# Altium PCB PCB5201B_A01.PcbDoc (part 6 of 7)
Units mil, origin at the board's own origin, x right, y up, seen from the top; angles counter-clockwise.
Board outline 4527.56 x 2362.2 mil, 6 copper layers (Top Layer, GND Layer 2, Signal Layer 3, Signal Layer 4, VCC Layer 5, Bottom Layer), stack 61.221 mil thick; 361 components, 250 nets, 1223 pads, 1068 vias.
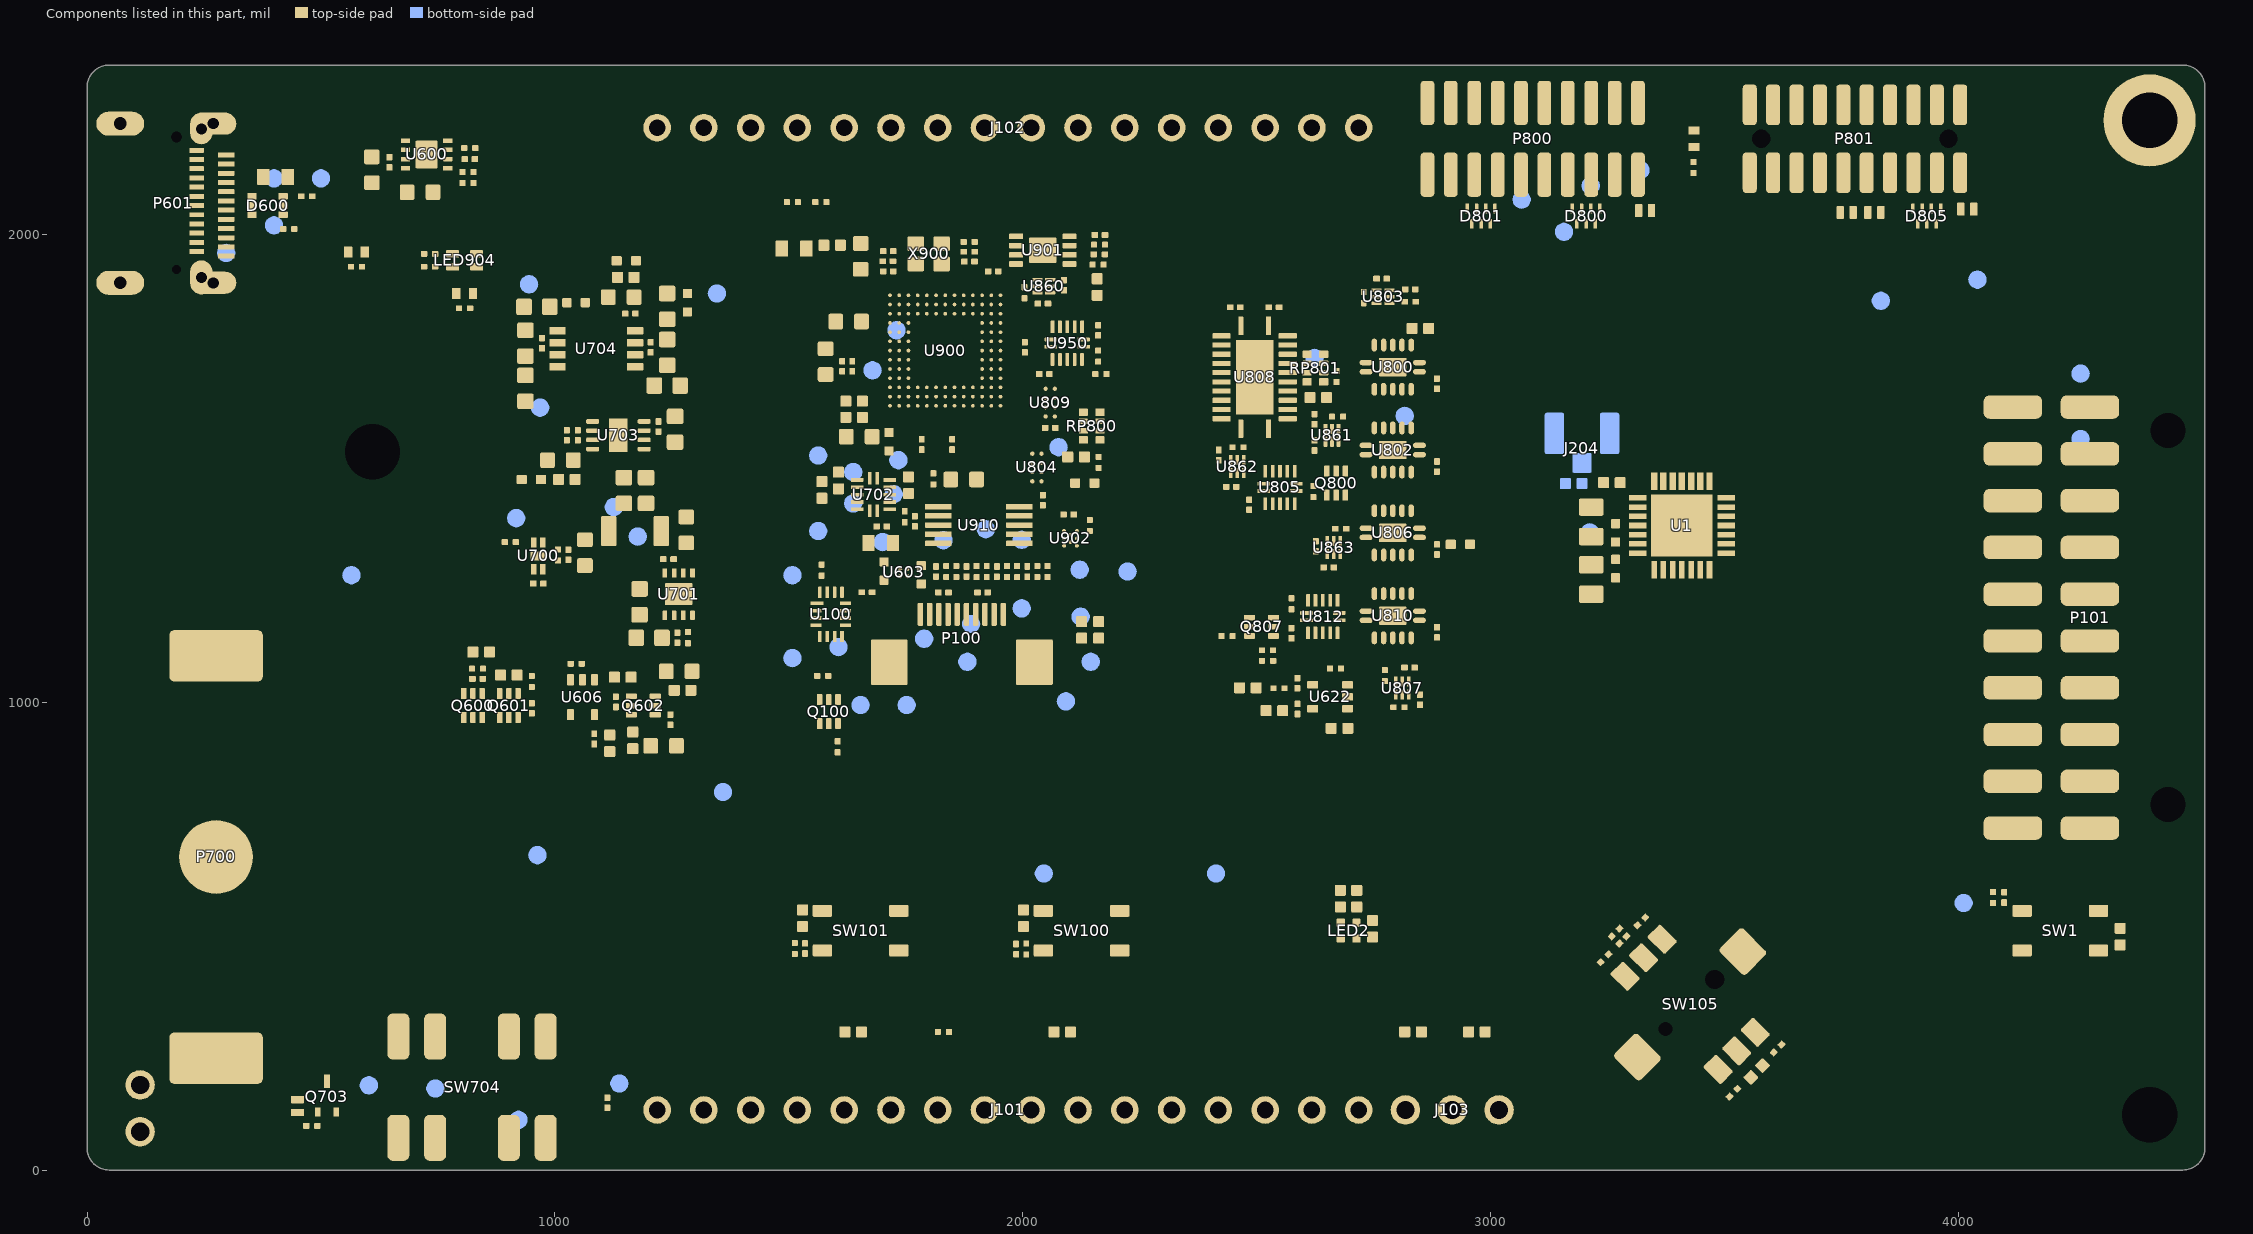
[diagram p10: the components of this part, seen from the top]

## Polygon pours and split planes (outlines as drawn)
VMCU on VCC Layer 5 "VMCU_L05_P027" (solid, remove dead copper, pour order 27): 3067.91,1562.99 3084.65,1579.72 4004.92,1579.72 4033.46,1608.27 4033.46,2333.66 4062.01,2362.2 4527.56,2362.2 4527.56,0 828.74,0 826.77,0 798.23,28.54 798.23,248.03 808.07,257.87 1142.72,257.87 1163.39,278.54 1163.39,914.37 1183.07,934.06 3031.5,934.06 3067.91,970.47
3V3 on VCC Layer 5 "3V3_L05_P024" (solid, remove dead copper, pour order 24): 337.6,1413.18 340.76,1416.34 706.69,1416.34 1187.01,1416.34 1322.83,1280.51 1633.86,1280.51 1752.41,1399.06 1752.41,1657.64 1680.76,1730.32 1482.28,1730.32 1422.93,1789.67 714.11,1789.67 612.2,1892.92 612.2,2059.05 628.54,2075.39 2514.37,2075.39 2694.94,2255.96 2781.74,2255.85 3058.36,1983.27 3765.75,1983.27 3913.39,2130.91 3913.39,2324.8 3930.12,2341.54 4013.78,2341.54 4024.61,2330.71 4024.61,1617.13 3997.05,1589.57 3074.8,1589.57 3056.1,1570.87 3057.09,1567.91 3057.09,975.39 3026.57,944.88 1175.2,944.88 1153.54,923.23 1153.54,914.37 1153.54,286.42 1153.54,284.45 1136.81,266.73 768.7,266.73 703.74,331.69 703.74,1040.35 337.6,1406.5
5V on VCC Layer 5 "5V_L05_P005" (solid, remove dead copper, pour order 5): 1676.18,1720.47 1475.88,1720.47 1416.86,1780.51 710.63,1780.51 604.33,1886.81 604.33,2062.99 625,2083.66 2508.86,2083.66 2690.94,2265.75 2786.42,2265.75 3061.02,1991.14 3763.78,1991.14 3907.48,2134.84 3907.48,2326.77 3893.7,2340.55 308.07,2340.55 301.18,2333.66 301.18,1440.94 316.93,1425.2 1191.93,1425.2 1326.77,1290.35 1629.92,1290.35 1743.11,1403.54 1743.11,1653.54
GND on VCC Layer 5 "VCC Layer 5-GND" (solid, remove dead copper, pour order 28): 19.68,19.68 757.87,19.68 767.72,29.53 767.72,227.36 673.23,321.85 673.23,1030.51 279.53,1424.21 279.53,2342.52 37.4,2342.52 19.68,2324.8 19.68,1393.7
GND on Top Layer "GND_L01_P021" (solid, remove dead copper, pour order 21): 0,0 0,2362.2 4921.26,2362.2 4921.26,0
USBC_VBUS on Top Layer "USBC_VBUS_L01_P020" (solid, remove dead copper, pour order 20): 387.8,2170.28 387.8,2109.25 347.44,2109.25 330.71,2125.98 330.71,2154.53 354.33,2178.15 382.55,2178.15
5V on Top Layer "5V_L01_P019" (solid, remove dead copper, pour order 19): 417.32,2107.28 417.32,2168.31 436.02,2187.01 469.49,2187.01 483.27,2173.23 483.27,2112.2 482.28,2112.2 477.36,2107.28 420.28,2107.28
5V on Top Layer "5V_L01_P018" (solid, remove dead copper, pour order 18): 565.94,2150.59 550.2,2166.34 550.2,2211.61 563.98,2225.39 644.68,2225.39 661.42,2208.66 661.42,2174.21 647.64,2160.43 619.09,2160.43 619.09,2153.54 616.14,2150.59
3V3 on Top Layer "3V3_L01_P017" (solid, remove dead copper, pour order 17): 670.28,2145.67 662.4,2137.8 662.4,2120.08 638.78,2096.46 638.78,2042.32 651.57,2029.53 706.69,2029.53 718.5,2041.34 718.5,2068.9 699.8,2087.6 699.8,2133.86 687.99,2145.67
VMCU_R on Top Layer "VMCU_R_L01_P016" (solid, remove dead copper, pour order 16): 1240.16,1267.72 1239.17,1268.7 1239.17,1291.34 1235.24,1295.28 1222.44,1295.28 1190.94,1326.77 1153.54,1326.77 1139.76,1312.99 1139.76,1282.48 1155.51,1266.73 1239.17,1266.73 1240.16,1267.72 1240.16,1268.7
VMCU_R on Top Layer "VMCU_R_L01_P015" (solid, remove dead copper, pour order 15): 1201.77,1396.65 1195.87,1390.75 1195.87,1348.43 1176.18,1328.74 1154.53,1328.74 1139.76,1313.98 1139.76,1307.09 1148.62,1298.23 1186.02,1298.23 1222.44,1334.65 1239.17,1334.65 1243.11,1338.58 1243.11,1396.65
VMCU_S on Top Layer "VMCU_S_L01_P014" (solid, remove dead copper, pour order 14): 1130.91,1397.64 1128.94,1395.67 1128.94,1335.63 1072.83,1335.63 1068.9,1331.69 1053.15,1331.69 1042.32,1320.87 1041.34,1321.85 995.08,1321.85 987.2,1329.72 987.2,1375.98 1007.87,1396.65 1125,1396.65 1125.98,1397.64
5V on Top Layer "5V_L01_P013" (solid, remove dead copper, pour order 13): 1248.03,1302.17 1248.03,1323.82 1265.75,1341.54 1265.75,1352.36 1269.68,1356.3 1309.06,1356.3 1327.76,1375 1340.55,1375 1351.38,1364.17 1351.38,1314.96 1331.69,1295.28 1269.69,1295.28 1262.8,1302.17
AEM_VMCU on Top Layer "AEM_VMCU_L01_P002" (solid, remove dead copper, pour order 2): 959.65,1294.29 958.66,1295.28 931.1,1295.28 917.32,1281.5 917.32,1245.08 909.45,1237.2 909.45,1220.47 918.31,1211.61 956.69,1211.61 966.54,1221.46 966.54,1240.16 959.65,1247.05
GND on Signal Layer 3 "GND_L03_P025" (solid, remove dead copper, pour order 25): 0,0 0,2362.2 4921.26,2362.2 4921.26,0
3V3 on Signal Layer 3 "3V3_L03_P022" (solid, remove dead copper, pour order 22): 714.57,2034.45 729.33,2049.21 729.33,2132.87 696.85,2165.35 696.85,2238.19 678.15,2256.89 641.73,2256.89 626.97,2242.13 626.97,2170.28 650.59,2146.65 650.59,2038.39 654.53,2034.45
GND on GND Layer 2 "GND_L02_P009" (solid, remove dead copper, pour order 9): 0,0 0,2362.2 4921.26,2362.2 4921.26,0
GND on Bottom Layer "GND_L06_P008" (solid, remove dead copper, pour order 8): 0,0 0,2362.2 4921.26,2362.2 4921.26,0
GND on Signal Layer 4 "GND_L04_P012" (solid, remove dead copper, pour order 12): 0,0 0,2362.2 4921.26,2362.2 4921.26,0

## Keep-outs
Bottom Layer:
  region: 500.01,2139.76 cw(c500.01,2120.07) 519.7,2120.08 cw(c500.01,2120.08) 500.01,2100.39 cw(c500.01,2120.07) 480.33,2120.07 cw(c500.02,2120.07)
  region: 1287.04,228.43 ccw(c1318.54,228.43) 1318.54,196.94 ccw(c1318.54,228.43) 1350.03,228.43 ccw(c1318.54,228.43) 1318.54,259.93 ccw(c1318.54,228.43)
  region: 1387.04,228.43 ccw(c1418.54,228.43) 1418.54,196.94 ccw(c1418.54,228.43) 1450.03,228.43 ccw(c1418.54,228.43) 1418.54,259.93 ccw(c1418.54,228.43)
  region: 1487.04,228.43 ccw(c1518.54,228.43) 1518.54,196.94 ccw(c1518.54,228.43) 1550.03,228.43 ccw(c1518.54,228.43) 1518.54,259.93 ccw(c1518.54,228.43)
  region: 1587.04,228.43 ccw(c1618.54,228.43) 1618.54,196.94 ccw(c1618.54,228.43) 1650.03,228.43 ccw(c1618.54,228.43) 1618.54,259.93 ccw(c1618.54,228.43)
  region: 1687.04,228.43 ccw(c1718.54,228.43) 1718.54,196.94 ccw(c1718.54,228.43) 1750.03,228.43 ccw(c1718.54,228.43) 1718.54,259.93 ccw(c1718.54,228.43)
  region: 1787.04,228.43 ccw(c1818.54,228.43) 1818.54,196.94 ccw(c1818.54,228.43) 1850.03,228.43 ccw(c1818.54,228.43) 1818.54,259.93 ccw(c1818.54,228.43)
  region: 1887.04,228.43 ccw(c1918.54,228.43) 1918.54,196.94 ccw(c1918.54,228.43) 1950.03,228.43 ccw(c1918.54,228.43) 1918.54,259.93 ccw(c1918.54,228.43)
  region: 1987.04,228.43 ccw(c2018.54,228.43) 2018.54,196.94 ccw(c2018.54,228.43) 2050.03,228.43 ccw(c2018.54,228.43) 2018.54,259.93 ccw(c2018.54,228.43)
  region: 2087.04,228.43 ccw(c2118.54,228.43) 2118.54,196.94 ccw(c2118.54,228.43) 2150.03,228.43 ccw(c2118.54,228.43) 2118.54,259.93 ccw(c2118.54,228.43)
  region: 2187.04,228.43 ccw(c2218.54,228.43) 2218.54,196.94 ccw(c2218.54,228.43) 2250.03,228.43 ccw(c2218.54,228.43) 2218.54,259.93 ccw(c2218.54,228.43)
  region: 2287.04,228.43 ccw(c2318.54,228.43) 2318.54,196.94 ccw(c2318.54,228.43) 2350.03,228.43 ccw(c2318.54,228.43) 2318.54,259.93 ccw(c2318.54,228.43)
  region: 2387.04,228.43 ccw(c2418.54,228.43) 2418.54,196.94 ccw(c2418.54,228.43) 2450.03,228.43 ccw(c2418.54,228.43) 2418.54,259.93 ccw(c2418.54,228.43)
  region: 2487.04,228.43 ccw(c2518.54,228.43) 2518.54,196.94 ccw(c2518.54,228.43) 2550.03,228.43 ccw(c2518.54,228.43) 2518.54,259.93 ccw(c2518.54,228.43)
  region: 2587.04,228.43 ccw(c2618.54,228.43) 2618.54,196.94 ccw(c2618.54,228.43) 2650.03,228.43 ccw(c2618.54,228.43) 2618.54,259.93 ccw(c2618.54,228.43)
  region: 2687.04,228.43 ccw(c2718.54,228.43) 2718.54,196.94 ccw(c2718.54,228.43) 2750.03,228.43 ccw(c2718.54,228.43) 2718.54,259.93 ccw(c2718.54,228.43)
  region: 1187.04,228.43 ccw(c1218.54,228.43) 1218.54,196.94 ccw(c1218.54,228.43) 1250.03,228.43 ccw(c1218.54,228.43) 1218.54,259.93 ccw(c1218.54,228.43)
  region: 1187.04,128.43 ccw(c1218.54,128.43) 1218.54,96.94 ccw(c1218.54,128.43) 1250.03,128.43 ccw(c1218.54,128.43) 1218.54,159.93 ccw(c1218.54,128.43)
  region: 1187.04,128.43 ccw(c1218.54,128.43) 1218.54,96.94 ccw(c1218.54,128.43) 1250.03,128.43 ccw(c1218.54,128.43) 1218.54,159.93 ccw(c1218.54,128.43)
  region: 1287.04,128.43 ccw(c1318.54,128.43) 1318.54,96.94 ccw(c1318.54,128.43) 1350.03,128.43 ccw(c1318.54,128.43) 1318.54,159.93 ccw(c1318.54,128.43)
  region: 1387.04,128.43 ccw(c1418.54,128.43) 1418.54,96.94 ccw(c1418.54,128.43) 1450.03,128.43 ccw(c1418.54,128.43) 1418.54,159.93 ccw(c1418.54,128.43)
  region: 1487.04,128.43 ccw(c1518.54,128.43) 1518.54,96.94 ccw(c1518.54,128.43) 1550.03,128.43 ccw(c1518.54,128.43) 1518.54,159.93 ccw(c1518.54,128.43)
  region: 1587.04,128.43 ccw(c1618.54,128.43) 1618.54,96.94 ccw(c1618.54,128.43) 1650.03,128.43 ccw(c1618.54,128.43) 1618.54,159.93 ccw(c1618.54,128.43)
  region: 1687.04,128.43 ccw(c1718.54,128.43) 1718.54,96.94 ccw(c1718.54,128.43) 1750.03,128.43 ccw(c1718.54,128.43) 1718.54,159.93 ccw(c1718.54,128.43)
  region: 1787.04,128.43 ccw(c1818.54,128.43) 1818.54,96.94 ccw(c1818.54,128.43) 1850.03,128.43 ccw(c1818.54,128.43) 1818.54,159.93 ccw(c1818.54,128.43)
  region: 1885.07,129.42 ccw(c1916.57,129.42) 1916.57,97.92 ccw(c1916.57,129.42) 1948.06,129.42 ccw(c1916.57,129.42) 1916.57,160.91 ccw(c1916.57,129.42)
  region: 1987.04,128.43 ccw(c2018.54,128.43) 2018.54,96.94 ccw(c2018.54,128.43) 2050.03,128.43 ccw(c2018.54,128.43) 2018.54,159.93 ccw(c2018.54,128.43)
  region: 2087.04,128.43 ccw(c2118.54,128.43) 2118.54,96.94 ccw(c2118.54,128.43) 2150.03,128.43 ccw(c2118.54,128.43) 2118.54,159.93 ccw(c2118.54,128.43)
  region: 2187.04,128.43 ccw(c2218.54,128.43) 2218.54,96.94 ccw(c2218.54,128.43) 2250.03,128.43 ccw(c2218.54,128.43) 2218.54,159.93 ccw(c2218.54,128.43)
  region: 2287.04,128.43 ccw(c2318.54,128.43) 2318.54,96.94 ccw(c2318.54,128.43) 2350.03,128.43 ccw(c2318.54,128.43) 2318.54,159.93 ccw(c2318.54,128.43)
  region: 2387.04,128.43 ccw(c2418.54,128.43) 2418.54,96.94 ccw(c2418.54,128.43) 2450.03,128.43 ccw(c2418.54,128.43) 2418.54,159.93 ccw(c2418.54,128.43)
  region: 2487.04,128.43 ccw(c2518.54,128.43) 2518.54,96.94 ccw(c2518.54,128.43) 2550.03,128.43 ccw(c2518.54,128.43) 2518.54,159.93 ccw(c2518.54,128.43)
  region: 2587.04,128.43 ccw(c2618.54,128.43) 2618.54,96.94 ccw(c2618.54,128.43) 2650.03,128.43 ccw(c2618.54,128.43) 2618.54,159.93 ccw(c2618.54,128.43)
  region: 2687.04,128.43 ccw(c2718.54,128.43) 2718.54,96.94 ccw(c2718.54,128.43) 2750.03,128.43 ccw(c2718.54,128.43) 2718.54,159.93 ccw(c2718.54,128.43)
  region: 1287.04,2228.43 ccw(c1318.54,2228.43) 1318.54,2196.94 ccw(c1318.54,2228.43) 1350.03,2228.43 ccw(c1318.54,2228.43) 1318.54,2259.93 ccw(c1318.54,2228.43)
  region: 1387.04,2228.43 ccw(c1418.54,2228.43) 1418.54,2196.94 ccw(c1418.54,2228.43) 1450.03,2228.43 ccw(c1418.54,2228.43) 1418.54,2259.93 ccw(c1418.54,2228.43)
  region: 1487.04,2228.43 ccw(c1518.54,2228.43) 1518.54,2196.94 ccw(c1518.54,2228.43) 1550.03,2228.43 ccw(c1518.54,2228.43) 1518.54,2259.93 ccw(c1518.54,2228.43)
  region: 1587.04,2228.43 ccw(c1618.54,2228.43) 1618.54,2196.94 ccw(c1618.54,2228.43) 1650.03,2228.43 ccw(c1618.54,2228.43) 1618.54,2259.93 ccw(c1618.54,2228.43)
  region: 1687.04,2228.43 ccw(c1718.54,2228.43) 1718.54,2196.94 ccw(c1718.54,2228.43) 1750.03,2228.43 ccw(c1718.54,2228.43) 1718.54,2259.93 ccw(c1718.54,2228.43)
  region: 1787.04,2228.43 ccw(c1818.54,2228.43) 1818.54,2196.94 ccw(c1818.54,2228.43) 1850.03,2228.43 ccw(c1818.54,2228.43) 1818.54,2259.93 ccw(c1818.54,2228.43)
  region: 1887.04,2228.43 ccw(c1918.54,2228.43) 1918.54,2196.94 ccw(c1918.54,2228.43) 1950.03,2228.43 ccw(c1918.54,2228.43) 1918.54,2259.93 ccw(c1918.54,2228.43)
  region: 1987.04,2228.43 ccw(c2018.54,2228.43) 2018.54,2196.94 ccw(c2018.54,2228.43) 2050.03,2228.43 ccw(c2018.54,2228.43) 2018.54,2259.93 ccw(c2018.54,2228.43)
  region: 2087.04,2228.43 ccw(c2118.54,2228.43) 2118.54,2196.94 ccw(c2118.54,2228.43) 2150.03,2228.43 ccw(c2118.54,2228.43) 2118.54,2259.93 ccw(c2118.54,2228.43)
  region: 2187.04,2228.43 ccw(c2218.54,2228.43) 2218.54,2196.94 ccw(c2218.54,2228.43) 2250.03,2228.43 ccw(c2218.54,2228.43) 2218.54,2259.93 ccw(c2218.54,2228.43)
  region: 2287.04,2228.43 ccw(c2318.54,2228.43) 2318.54,2196.94 ccw(c2318.54,2228.43) 2350.03,2228.43 ccw(c2318.54,2228.43) 2318.54,2259.93 ccw(c2318.54,2228.43)
  region: 2387.04,2228.43 ccw(c2418.54,2228.43) 2418.54,2196.94 ccw(c2418.54,2228.43) 2450.03,2228.43 ccw(c2418.54,2228.43) 2418.54,2259.93 ccw(c2418.54,2228.43)
  region: 2487.04,2228.43 ccw(c2518.54,2228.43) 2518.54,2196.94 ccw(c2518.54,2228.43) 2550.03,2228.43 ccw(c2518.54,2228.43) 2518.54,2259.93 ccw(c2518.54,2228.43)
  region: 2587.04,2228.43 ccw(c2618.54,2228.43) 2618.54,2196.94 ccw(c2618.54,2228.43) 2650.03,2228.43 ccw(c2618.54,2228.43) 2618.54,2259.93 ccw(c2618.54,2228.43)
  region: 2687.04,2228.43 ccw(c2718.54,2228.43) 2718.54,2196.94 ccw(c2718.54,2228.43) 2750.03,2228.43 ccw(c2718.54,2228.43) 2718.54,2259.93 ccw(c2718.54,2228.43)
  region: 1187.04,2228.43 ccw(c1218.54,2228.43) 1218.54,2196.94 ccw(c1218.54,2228.43) 1250.03,2228.43 ccw(c1218.54,2228.43) 1218.54,2259.93 ccw(c1218.54,2228.43)
  region: 1187.04,2128.43 ccw(c1218.54,2128.43) 1218.54,2096.94 ccw(c1218.54,2128.43) 1250.03,2128.43 ccw(c1218.54,2128.43) 1218.54,2159.93 ccw(c1218.54,2128.43)
  region: 1187.04,2128.43 ccw(c1218.54,2128.43) 1218.54,2096.94 ccw(c1218.54,2128.43) 1250.03,2128.43 ccw(c1218.54,2128.43) 1218.54,2159.93 ccw(c1218.54,2128.43)
  region: 1287.04,2128.43 ccw(c1318.54,2128.43) 1318.54,2096.94 ccw(c1318.54,2128.43) 1350.03,2128.43 ccw(c1318.54,2128.43) 1318.54,2159.93 ccw(c1318.54,2128.43)
  region: 1387.04,2128.43 ccw(c1418.54,2128.43) 1418.54,2096.94 ccw(c1418.54,2128.43) 1450.03,2128.43 ccw(c1418.54,2128.43) 1418.54,2159.93 ccw(c1418.54,2128.43)
  region: 1487.04,2128.43 ccw(c1518.54,2128.43) 1518.54,2096.94 ccw(c1518.54,2128.43) 1550.03,2128.43 ccw(c1518.54,2128.43) 1518.54,2159.93 ccw(c1518.54,2128.43)
  region: 1587.04,2128.43 ccw(c1618.54,2128.43) 1618.54,2096.94 ccw(c1618.54,2128.43) 1650.03,2128.43 ccw(c1618.54,2128.43) 1618.54,2159.93 ccw(c1618.54,2128.43)
  region: 1687.04,2128.43 ccw(c1718.54,2128.43) 1718.54,2096.94 ccw(c1718.54,2128.43) 1750.03,2128.43 ccw(c1718.54,2128.43) 1718.54,2159.93 ccw(c1718.54,2128.43)
  region: 1787.04,2128.43 ccw(c1818.54,2128.43) 1818.54,2096.94 ccw(c1818.54,2128.43) 1850.03,2128.43 ccw(c1818.54,2128.43) 1818.54,2159.93 ccw(c1818.54,2128.43)
  region: 1887.04,2128.43 ccw(c1918.54,2128.43) 1918.54,2096.94 ccw(c1918.54,2128.43) 1950.03,2128.43 ccw(c1918.54,2128.43) 1918.54,2159.93 ccw(c1918.54,2128.43)
  region: 1987.04,2128.43 ccw(c2018.54,2128.43) 2018.54,2096.94 ccw(c2018.54,2128.43) 2050.03,2128.43 ccw(c2018.54,2128.43) 2018.54,2159.93 ccw(c2018.54,2128.43)
  region: 2087.04,2128.43 ccw(c2118.54,2128.43) 2118.54,2096.94 ccw(c2118.54,2128.43) 2150.03,2128.43 ccw(c2118.54,2128.43) 2118.54,2159.93 ccw(c2118.54,2128.43)
  region: 2187.04,2128.43 ccw(c2218.54,2128.43) 2218.54,2096.94 ccw(c2218.54,2128.43) 2250.03,2128.43 ccw(c2218.54,2128.43) 2218.54,2159.93 ccw(c2218.54,2128.43)
  region: 2287.04,2128.43 ccw(c2318.54,2128.43) 2318.54,2096.94 ccw(c2318.54,2128.43) 2350.03,2128.43 ccw(c2318.54,2128.43) 2318.54,2159.93 ccw(c2318.54,2128.43)
  region: 2387.04,2128.43 ccw(c2418.54,2128.43) 2418.54,2096.94 ccw(c2418.54,2128.43) 2450.03,2128.43 ccw(c2418.54,2128.43) 2418.54,2159.93 ccw(c2418.54,2128.43)
  region: 2487.04,2128.43 ccw(c2518.54,2128.43) 2518.54,2096.94 ccw(c2518.54,2128.43) 2550.03,2128.43 ccw(c2518.54,2128.43) 2518.54,2159.93 ccw(c2518.54,2128.43)
  region: 2587.04,2128.43 ccw(c2618.54,2128.43) 2618.54,2096.94 ccw(c2618.54,2128.43) 2650.03,2128.43 ccw(c2618.54,2128.43) 2618.54,2159.93 ccw(c2618.54,2128.43)
  region: 2687.04,2128.43 ccw(c2718.54,2128.43) 2718.54,2096.94 ccw(c2718.54,2128.43) 2750.03,2128.43 ccw(c2718.54,2128.43) 2718.54,2159.93 ccw(c2718.54,2128.43)
  region: 1787.04,2128.43 ccw(c1818.54,2128.43) 1818.54,2096.94 ccw(c1818.54,2128.43) 1850.03,2128.43 ccw(c1818.54,2128.43) 1818.54,2159.93 ccw(c1818.54,2128.43)
  region: 1687.04,2128.43 ccw(c1718.54,2128.43) 1718.54,2096.94 ccw(c1718.54,2128.43) 1750.03,2128.43 ccw(c1718.54,2128.43) 1718.54,2159.93 ccw(c1718.54,2128.43)
  region: 1587.04,2128.43 ccw(c1618.54,2128.43) 1618.54,2096.94 ccw(c1618.54,2128.43) 1650.03,2128.43 ccw(c1618.54,2128.43) 1618.54,2159.93 ccw(c1618.54,2128.43)
  region: 1487.04,2128.43 ccw(c1518.54,2128.43) 1518.54,2096.94 ccw(c1518.54,2128.43) 1550.03,2128.43 ccw(c1518.54,2128.43) 1518.54,2159.93 ccw(c1518.54,2128.43)
  region: 1387.04,2128.43 ccw(c1418.54,2128.43) 1418.54,2096.94 ccw(c1418.54,2128.43) 1450.03,2128.43 ccw(c1418.54,2128.43) 1418.54,2159.93 ccw(c1418.54,2128.43)
  region: 1287.04,2128.43 ccw(c1318.54,2128.43) 1318.54,2096.94 ccw(c1318.54,2128.43) 1350.03,2128.43 ccw(c1318.54,2128.43) 1318.54,2159.93 ccw(c1318.54,2128.43)
  region: 1187.04,2128.43 ccw(c1218.54,2128.43) 1218.54,2096.94 ccw(c1218.54,2128.43) 1250.03,2128.43 ccw(c1218.54,2128.43) 1218.54,2159.93 ccw(c1218.54,2128.43)
  region: 1187.04,2128.43 ccw(c1218.54,2128.43) 1218.54,2096.94 ccw(c1218.54,2128.43) 1250.03,2128.43 ccw(c1218.54,2128.43) 1218.54,2159.93 ccw(c1218.54,2128.43)
  region: 1187.04,2228.43 ccw(c1218.54,2228.43) 1218.54,2196.94 ccw(c1218.54,2228.43) 1250.03,2228.43 ccw(c1218.54,2228.43) 1218.54,2259.93 ccw(c1218.54,2228.43)
  region: 1787.04,2228.43 ccw(c1818.54,2228.43) 1818.54,2196.94 ccw(c1818.54,2228.43) 1850.03,2228.43 ccw(c1818.54,2228.43) 1818.54,2259.93 ccw(c1818.54,2228.43)
  region: 1687.04,2228.43 ccw(c1718.54,2228.43) 1718.54,2196.94 ccw(c1718.54,2228.43) 1750.03,2228.43 ccw(c1718.54,2228.43) 1718.54,2259.93 ccw(c1718.54,2228.43)
  region: 1587.04,2228.43 ccw(c1618.54,2228.43) 1618.54,2196.94 ccw(c1618.54,2228.43) 1650.03,2228.43 ccw(c1618.54,2228.43) 1618.54,2259.93 ccw(c1618.54,2228.43)
  region: 1487.04,2228.43 ccw(c1518.54,2228.43) 1518.54,2196.94 ccw(c1518.54,2228.43) 1550.03,2228.43 ccw(c1518.54,2228.43) 1518.54,2259.93 ccw(c1518.54,2228.43)
  region: 1387.04,2228.43 ccw(c1418.54,2228.43) 1418.54,2196.94 ccw(c1418.54,2228.43) 1450.03,2228.43 ccw(c1418.54,2228.43) 1418.54,2259.93 ccw(c1418.54,2228.43)
  region: 1287.04,2228.43 ccw(c1318.54,2228.43) 1318.54,2196.94 ccw(c1318.54,2228.43) 1350.03,2228.43 ccw(c1318.54,2228.43) 1318.54,2259.93 ccw(c1318.54,2228.43)
  region: 2687.04,128.43 ccw(c2718.54,128.43) 2718.54,96.94 ccw(c2718.54,128.43) 2750.03,128.43 ccw(c2718.54,128.43) 2718.54,159.93 ccw(c2718.54,128.43)
  region: 2587.04,128.43 ccw(c2618.54,128.43) 2618.54,96.94 ccw(c2618.54,128.43) 2650.03,128.43 ccw(c2618.54,128.43) 2618.54,159.93 ccw(c2618.54,128.43)
  region: 2387.04,128.43 ccw(c2418.54,128.43) 2418.54,96.94 ccw(c2418.54,128.43) 2450.03,128.43 ccw(c2418.54,128.43) 2418.54,159.93 ccw(c2418.54,128.43)
  region: 2287.04,128.43 ccw(c2318.54,128.43) 2318.54,96.94 ccw(c2318.54,128.43) 2350.03,128.43 ccw(c2318.54,128.43) 2318.54,159.93 ccw(c2318.54,128.43)
  region: 1587.04,128.43 ccw(c1618.54,128.43) 1618.54,96.94 ccw(c1618.54,128.43) 1650.03,128.43 ccw(c1618.54,128.43) 1618.54,159.93 ccw(c1618.54,128.43)
  region: 1487.04,128.43 ccw(c1518.54,128.43) 1518.54,96.94 ccw(c1518.54,128.43) 1550.03,128.43 ccw(c1518.54,128.43) 1518.54,159.93 ccw(c1518.54,128.43)
  region: 1387.04,128.43 ccw(c1418.54,128.43) 1418.54,96.94 ccw(c1418.54,128.43) 1450.03,128.43 ccw(c1418.54,128.43) 1418.54,159.93 ccw(c1418.54,128.43)
  region: 1287.04,128.43 ccw(c1318.54,128.43) 1318.54,96.94 ccw(c1318.54,128.43) 1350.03,128.43 ccw(c1318.54,128.43) 1318.54,159.93 ccw(c1318.54,128.43)
  region: 1187.04,128.43 ccw(c1218.54,128.43) 1218.54,96.94 ccw(c1218.54,128.43) 1250.03,128.43 ccw(c1218.54,128.43) 1218.54,159.93 ccw(c1218.54,128.43)
  region: 1187.04,128.43 ccw(c1218.54,128.43) 1218.54,96.94 ccw(c1218.54,128.43) 1250.03,128.43 ccw(c1218.54,128.43) 1218.54,159.93 ccw(c1218.54,128.43)
  region: 1187.04,228.43 ccw(c1218.54,228.43) 1218.54,196.94 ccw(c1218.54,228.43) 1250.03,228.43 ccw(c1218.54,228.43) 1218.54,259.93 ccw(c1218.54,228.43)
  region: 2687.04,228.43 ccw(c2718.54,228.43) 2718.54,196.94 ccw(c2718.54,228.43) 2750.03,228.43 ccw(c2718.54,228.43) 2718.54,259.93 ccw(c2718.54,228.43)
  region: 2587.04,228.43 ccw(c2618.54,228.43) 2618.54,196.94 ccw(c2618.54,228.43) 2650.03,228.43 ccw(c2618.54,228.43) 2618.54,259.93 ccw(c2618.54,228.43)
  region: 2487.04,228.43 ccw(c2518.54,228.43) 2518.54,196.94 ccw(c2518.54,228.43) 2550.03,228.43 ccw(c2518.54,228.43) 2518.54,259.93 ccw(c2518.54,228.43)
  region: 2387.04,228.43 ccw(c2418.54,228.43) 2418.54,196.94 ccw(c2418.54,228.43) 2450.03,228.43 ccw(c2418.54,228.43) 2418.54,259.93 ccw(c2418.54,228.43)
  region: 2287.04,228.43 ccw(c2318.54,228.43) 2318.54,196.94 ccw(c2318.54,228.43) 2350.03,228.43 ccw(c2318.54,228.43) 2318.54,259.93 ccw(c2318.54,228.43)
  region: 1587.04,228.43 ccw(c1618.54,228.43) 1618.54,196.94 ccw(c1618.54,228.43) 1650.03,228.43 ccw(c1618.54,228.43) 1618.54,259.93 ccw(c1618.54,228.43)
  region: 1487.04,228.43 ccw(c1518.54,228.43) 1518.54,196.94 ccw(c1518.54,228.43) 1550.03,228.43 ccw(c1518.54,228.43) 1518.54,259.93 ccw(c1518.54,228.43)
  region: 1387.04,228.43 ccw(c1418.54,228.43) 1418.54,196.94 ccw(c1418.54,228.43) 1450.03,228.43 ccw(c1418.54,228.43) 1418.54,259.93 ccw(c1418.54,228.43)
  region: 1287.04,228.43 ccw(c1318.54,228.43) 1318.54,196.94 ccw(c1318.54,228.43) 1350.03,228.43 ccw(c1318.54,228.43) 1318.54,259.93 ccw(c1318.54,228.43)
  region: 4074.8,748.03 cw(c4074.8,728.34) 4094.49,728.35 cw(c4074.8,728.35) 4074.8,708.66 cw(c4074.8,728.34) 4055.12,728.34 cw(c4074.81,728.34)
  region: 4261.81,1582.66 cw(c4261.81,1562.97) 4281.5,1562.98 cw(c4261.81,1562.98) 4261.81,1543.29 cw(c4261.81,1562.97) 4242.13,1562.97 cw(c4261.82,1562.97)
  region: 4261.81,1722.36 cw(c4261.81,1702.67) 4281.5,1702.68 cw(c4261.81,1702.68) 4261.81,1682.99 cw(c4261.81,1702.67) 4242.13,1702.67 cw(c4261.82,1702.67)
  region: 4212.61,2133.86 cw(c4212.61,2114.17) 4232.3,2114.18 cw(c4212.61,2114.18) 4212.61,2094.49 cw(c4212.61,2114.17) 4192.93,2114.17 cw(c4212.62,2114.17)
  region: 4149.61,2066.86 cw(c4149.61,2047.17) 4169.3,2047.18 cw(c4149.61,2047.18) 4149.61,2027.49 cw(c4149.61,2047.17) 4129.93,2047.17 cw(c4149.62,2047.17)
  region: 4112.21,2133.86 cw(c4112.21,2114.17) 4131.9,2114.18 cw(c4112.21,2114.18) 4112.21,2094.49 cw(c4112.21,2114.17) 4092.53,2114.17 cw(c4112.22,2114.17)
  region: 4070.81,2066.86 cw(c4070.81,2047.17) 4090.5,2047.18 cw(c4070.81,2047.18) 4070.81,2027.49 cw(c4070.81,2047.17) 4051.13,2047.17 cw(c4070.82,2047.17)
  region: 4041.31,1923.16 cw(c4041.31,1903.47) 4061,1903.48 cw(c4041.31,1903.48) 4041.31,1883.79 cw(c4041.31,1903.47) 4021.63,1903.47 cw(c4041.32,1903.47)
  region: 3834.61,1877.96 cw(c3834.61,1858.27) 3854.3,1858.28 cw(c3834.61,1858.28) 3834.61,1838.59 cw(c3834.61,1858.27) 3814.93,1858.27 cw(c3834.62,1858.27)
  region: 3642.71,2064.26 cw(c3642.71,2044.57) 3662.4,2044.58 cw(c3642.71,2044.58) 3642.71,2024.89 cw(c3642.71,2044.57) 3623.03,2044.57 cw(c3642.72,2044.57)
  region: 3682.71,2134.26 cw(c3682.71,2114.57) 3702.4,2114.58 cw(c3682.71,2114.58) 3682.71,2094.89 cw(c3682.71,2114.57) 3663.03,2114.57 cw(c3682.72,2114.57)
  region: 3562.71,2064.26 cw(c3562.71,2044.57) 3582.4,2044.58 cw(c3562.71,2044.58) 3562.71,2024.89 cw(c3562.71,2044.57) 3543.03,2044.57 cw(c3562.72,2044.57)
  region: 3482.71,2064.26 cw(c3482.71,2044.57) 3502.4,2044.58 cw(c3482.71,2044.58) 3482.71,2024.89 cw(c3482.71,2044.57) 3463.03,2044.57 cw(c3482.72,2044.57)
  region: 3522.71,2134.26 cw(c3522.71,2114.57) 3542.4,2114.58 cw(c3522.71,2114.58) 3522.71,2094.89 cw(c3522.71,2114.57) 3503.03,2114.57 cw(c3522.72,2114.57)
  region: 3443.56,2134.11 cw(c3443.56,2114.42) 3463.25,2114.43 cw(c3443.56,2114.43) 3443.56,2094.74 cw(c3443.56,2114.42) 3423.88,2114.42 cw(c3443.57,2114.42)
  region: 3320.81,2157.46 cw(c3320.81,2137.77) 3340.5,2137.78 cw(c3320.81,2137.78) 3320.81,2118.09 cw(c3320.81,2137.77) 3301.13,2137.77 cw(c3320.82,2137.77)
  region: 3362.21,2055.06 cw(c3362.21,2035.37) 3381.9,2035.38 cw(c3362.21,2035.38) 3362.21,2015.69 cw(c3362.21,2035.37) 3342.53,2035.37 cw(c3362.22,2035.37)
  region: 3679.11,1684.96 cw(c3679.11,1665.27) 3698.8,1665.28 cw(c3679.11,1665.28) 3679.11,1645.59 cw(c3679.11,1665.27) 3659.43,1665.27 cw(c3679.12,1665.27)
  region: 3391.71,1576.76 cw(c3391.71,1557.07) 3411.4,1557.08 cw(c3391.71,1557.08) 3391.71,1537.39 cw(c3391.71,1557.07) 3372.03,1557.07 cw(c3391.72,1557.07)
  region: 3214.51,2123.96 cw(c3214.51,2104.27) 3234.2,2104.28 cw(c3214.51,2104.28) 3214.51,2084.59 cw(c3214.51,2104.27) 3194.83,2104.27 cw(c3214.52,2104.27)
  region: 3066.91,2094.46 cw(c3066.91,2074.77) 3086.6,2074.78 cw(c3066.91,2074.78) 3066.91,2055.09 cw(c3066.91,2074.77) 3047.23,2074.77 cw(c3066.92,2074.77)
  region: 3157.51,2025.56 cw(c3157.51,2005.87) 3177.2,2005.88 cw(c3157.51,2005.88) 3157.51,1986.19 cw(c3157.51,2005.87) 3137.83,2005.87 cw(c3157.52,2005.87)
  region: 3047.21,1909.36 cw(c3047.21,1889.67) 3066.9,1889.68 cw(c3047.21,1889.68) 3047.21,1869.99 cw(c3047.21,1889.67) 3027.53,1889.67 cw(c3047.22,1889.67)
  region: 2968.51,1909.36 cw(c2968.51,1889.67) 2988.2,1889.68 cw(c2968.51,1889.68) 2968.51,1869.99 cw(c2968.51,1889.67) 2948.83,1889.67 cw(c2968.52,1889.67)
  region: 2889.71,1909.36 cw(c2889.71,1889.67) 2909.4,1889.68 cw(c2889.71,1889.68) 2889.71,1869.99 cw(c2889.71,1889.67) 2870.03,1889.67 cw(c2889.72,1889.67)
  region: 3047.21,1822.76 cw(c3047.21,1803.07) 3066.9,1803.08 cw(c3047.21,1803.08) 3047.21,1783.39 cw(c3047.21,1803.07) 3027.53,1803.07 cw(c3047.22,1803.07)
  region: 2968.51,1822.76 cw(c2968.51,1803.07) 2988.2,1803.08 cw(c2968.51,1803.08) 2968.51,1783.39 cw(c2968.51,1803.07) 2948.83,1803.07 cw(c2968.52,1803.07)
  region: 2889.71,1822.76 cw(c2889.71,1803.07) 2909.4,1803.08 cw(c2889.71,1803.08) 2889.71,1783.39 cw(c2889.71,1803.07) 2870.03,1803.07 cw(c2889.72,1803.07)
  region: 2811.01,1822.76 cw(c2811.01,1803.07) 2830.7,1803.08 cw(c2811.01,1803.08) 2811.01,1783.39 cw(c2811.01,1803.07) 2791.33,1803.07 cw(c2811.02,1803.07)
  region: 2889.71,1716.46 cw(c2889.71,1696.77) 2909.4,1696.78 cw(c2889.71,1696.78) 2889.71,1677.09 cw(c2889.71,1696.77) 2870.03,1696.77 cw(c2889.72,1696.77)
  region: 2816.91,1631.86 cw(c2816.91,1612.17) 2836.6,1612.18 cw(c2816.91,1612.18) 2816.91,1592.49 cw(c2816.91,1612.17) 2797.23,1612.17 cw(c2816.92,1612.17)
  region: 2624.01,1755.86 cw(c2624.01,1736.17) 2643.7,1736.18 cw(c2624.01,1736.18) 2624.01,1716.49 cw(c2624.01,1736.17) 2604.33,1736.17 cw(c2624.02,1736.17)
  region: 3708.61,486.16 cw(c3708.61,466.47) 3728.3,466.48 cw(c3708.61,466.48) 3708.61,446.79 cw(c3708.61,466.47) 3688.93,466.47 cw(c3708.62,466.47)
  region: 3811.01,464.56 cw(c3811.01,444.87) 3830.7,444.88 cw(c3811.01,444.88) 3811.01,425.19 cw(c3811.01,444.87) 3791.33,444.87 cw(c3811.02,444.87)
  region: 3671.21,391.66 cw(c3671.21,371.97) 3690.9,371.98 cw(c3671.21,371.98) 3671.21,352.29 cw(c3671.21,371.97) 3651.53,371.97 cw(c3671.22,371.97)
  region: 3799.21,360.16 cw(c3799.21,340.47) 3818.9,340.48 cw(c3799.21,340.48) 3799.21,320.79 cw(c3799.21,340.47) 3779.53,340.47 cw(c3799.22,340.47)
  region: 3767.71,257.86 cw(c3767.71,238.17) 3787.4,238.18 cw(c3767.71,238.18) 3767.71,218.49 cw(c3767.71,238.17) 3748.03,238.17 cw(c3767.72,238.17)
  region: 3671.21,291.26 cw(c3671.21,271.57) 3690.9,271.58 cw(c3671.21,271.58) 3671.21,251.89 cw(c3671.21,271.57) 3651.53,271.57 cw(c3671.22,271.57)
  region: 3208.61,431.06 cw(c3208.61,411.37) 3228.3,411.38 cw(c3208.61,411.38) 3208.61,391.69 cw(c3208.61,411.37) 3188.93,411.37 cw(c3208.62,411.37)
  region: 3041.31,431.06 cw(c3041.31,411.37) 3061,411.38 cw(c3041.31,411.38) 3041.31,391.69 cw(c3041.31,411.37) 3021.63,411.37 cw(c3041.32,411.37)
  region: 2872.01,431.06 cw(c2872.01,411.37) 2891.7,411.38 cw(c2872.01,411.38) 2872.01,391.69 cw(c2872.01,411.37) 2852.33,411.37 cw(c2872.02,411.37)
  region: 2917.31,265.66 cw(c2917.31,245.97) 2937,245.98 cw(c2917.31,245.98) 2917.31,226.29 cw(c2917.31,245.97) 2897.63,245.97 cw(c2917.32,245.97)
  region: 2152.51,1638.76 cw(c2152.51,1619.07) 2172.2,1619.08 cw(c2152.51,1619.08) 2152.51,1599.39 cw(c2152.51,1619.07) 2132.83,1619.07 cw(c2152.52,1619.07)
  region: 2076.71,1564.96 cw(c2076.71,1545.27) 2096.4,1545.28 cw(c2076.71,1545.28) 2076.71,1525.59 cw(c2076.71,1545.27) 2057.03,1545.27 cw(c2076.72,1545.27)
  region: 1998.01,1367.06 cw(c1998.01,1347.37) 2017.7,1347.38 cw(c1998.01,1347.38) 1998.01,1327.69 cw(c1998.01,1347.37) 1978.33,1347.37 cw(c1998.02,1347.37)
  region: 2122.01,1303.06 cw(c2122.01,1283.37) 2141.7,1283.38 cw(c2122.01,1283.38) 2122.01,1263.69 cw(c2122.01,1283.37) 2102.33,1283.37 cw(c2122.02,1283.37)
  region: 1998.01,1220.46 cw(c1998.01,1200.77) 2017.7,1200.78 cw(c1998.01,1200.78) 1998.01,1181.09 cw(c1998.01,1200.77) 1978.33,1200.77 cw(c1998.02,1200.77)
  region: 2124.01,1202.76 cw(c2124.01,1183.07) 2143.7,1183.08 cw(c2124.01,1183.08) 2124.01,1163.39 cw(c2124.01,1183.07) 2104.33,1183.07 cw(c2124.02,1183.07)
  region: 2145.61,1106.26 cw(c2145.61,1086.57) 2165.3,1086.58 cw(c2145.61,1086.58) 2145.61,1066.89 cw(c2145.61,1086.57) 2125.93,1086.57 cw(c2145.62,1086.57)
  region: 2039.31,1106.26 cw(c2039.31,1086.57) 2059,1086.58 cw(c2039.31,1086.58) 2039.31,1066.89 cw(c2039.31,1086.57) 2019.63,1086.57 cw(c2039.32,1086.57)
  region: 2092.51,1021.66 cw(c2092.51,1001.97) 2112.2,1001.98 cw(c2092.51,1001.98) 2092.51,982.29 cw(c2092.51,1001.97) 2072.83,1001.97 cw(c2092.52,1001.97)
  region: 1889.71,1186.96 cw(c1889.71,1167.27) 1909.4,1167.28 cw(c1889.71,1167.28) 1889.71,1147.59 cw(c1889.71,1167.27) 1870.03,1167.27 cw(c1889.72,1167.27)
  region: 1789.31,1155.46 cw(c1789.31,1135.77) 1809,1135.78 cw(c1789.31,1135.78) 1789.31,1116.09 cw(c1789.31,1135.77) 1769.63,1135.77 cw(c1789.32,1135.77)
  region: 1850.41,1013.76 cw(c1850.41,994.07) 1870.1,994.08 cw(c1850.41,994.08) 1850.41,974.39 cw(c1850.41,994.07) 1830.73,994.07 cw(c1850.42,994.07)
  region: 1702.71,1102.36 cw(c1702.71,1082.67) 1722.4,1082.68 cw(c1702.71,1082.68) 1702.71,1062.99 cw(c1702.71,1082.67) 1683.03,1082.67 cw(c1702.72,1082.67)
  region: 1751.91,1013.76 cw(c1751.91,994.07) 1771.6,994.08 cw(c1751.91,994.08) 1751.91,974.39 cw(c1751.91,994.07) 1732.23,994.07 cw(c1751.92,994.07)
  region: 1653.51,1013.76 cw(c1653.51,994.07) 1673.2,994.08 cw(c1653.51,994.08) 1653.51,974.39 cw(c1653.51,994.07) 1633.83,994.07 cw(c1653.52,994.07)
  region: 2413.41,653.46 cw(c2413.41,633.77) 2433.1,633.78 cw(c2413.41,633.78) 2413.41,614.09 cw(c2413.41,633.77) 2393.73,633.77 cw(c2413.42,633.77)
  region: 2045.31,653.46 cw(c2045.31,633.77) 2065,633.78 cw(c2045.31,633.78) 2045.31,614.09 cw(c2045.31,633.77) 2025.63,633.77 cw(c2045.32,633.77)
  region: 1359.21,827.76 cw(c1359.21,808.07) 1378.9,808.08 cw(c1359.21,808.08) 1359.21,788.39 cw(c1359.21,808.07) 1339.53,808.07 cw(c1359.22,808.07)
  region: 962.61,692.86 cw(c962.61,673.17) 982.3,673.18 cw(c962.61,673.18) 962.61,653.49 cw(c962.61,673.17) 942.93,673.17 cw(c962.62,673.17)
  region: 616.11,1041.26 cw(c616.11,1021.57) 635.8,1021.58 cw(c616.11,1021.58) 616.11,1001.89 cw(c616.11,1021.57) 596.43,1021.57 cw(c616.12,1021.57)
  region: 474.41,1041.26 cw(c474.41,1021.57) 494.1,1021.58 cw(c474.41,1021.58) 474.41,1001.89 cw(c474.41,1021.57) 454.73,1021.57 cw(c474.42,1021.57)
  region: 473.41,1172.16 cw(c473.41,1152.47) 493.1,1152.48 cw(c473.41,1152.48) 473.41,1132.79 cw(c473.41,1152.47) 453.73,1152.47 cw(c473.42,1152.47)
  region: 373.01,1173.16 cw(c373.01,1153.47) 392.7,1153.48 cw(c373.01,1153.48) 373.01,1133.79 cw(c373.01,1153.47) 353.33,1153.47 cw(c373.02,1153.47)
  region: 564.91,1291.26 cw(c564.91,1271.57) 584.6,1271.58 cw(c564.91,1271.58) 564.91,1251.89 cw(c564.91,1271.57) 545.23,1271.57 cw(c564.92,1271.57)
  region: 409.41,1269.66 cw(c409.41,1249.97) 429.1,1249.98 cw(c409.41,1249.98) 409.41,1230.29 cw(c409.41,1249.97) 389.73,1249.97 cw(c409.42,1249.97)
  region: 409.41,1373.96 cw(c409.41,1354.27) 429.1,1354.28 cw(c409.41,1354.28) 409.41,1334.59 cw(c409.41,1354.27) 389.73,1354.27 cw(c409.42,1354.27)
  region: 726.21,1930.86 cw(c726.21,1911.17) 745.9,1911.18 cw(c726.21,1911.18) 726.21,1891.49 cw(c726.21,1911.17) 706.53,1911.17 cw(c726.22,1911.17)
  region: 626.21,1980.86 cw(c626.21,1961.17) 645.9,1961.18 cw(c626.21,1961.18) 626.21,1941.49 cw(c626.21,1961.17) 606.53,1961.17 cw(c626.22,1961.17)
  region: 726.21,2030.86 cw(c726.21,2011.17) 745.9,2011.18 cw(c726.21,2011.18) 726.21,1991.49 cw(c726.21,2011.17) 706.53,2011.17 cw(c726.22,2011.17)
  region: 626.21,2080.86 cw(c626.21,2061.17) 645.9,2061.18 cw(c626.21,2061.18) 626.21,2041.49 cw(c626.21,2061.17) 606.53,2061.17 cw(c626.22,2061.17)
  region: 726.21,2130.86 cw(c726.21,2111.17) 745.9,2111.18 cw(c726.21,2111.18) 726.21,2091.49 cw(c726.21,2111.17) 706.53,2111.17 cw(c726.22,2111.17)
  region: 626.21,2180.86 cw(c626.21,2161.17) 645.9,2161.18 cw(c626.21,2161.18) 626.21,2141.49 cw(c626.21,2161.17) 606.53,2161.17 cw(c626.22,2161.17)
  region: 399.61,2139.76 cw(c399.61,2120.07) 419.3,2120.08 cw(c399.61,2120.08) 399.61,2100.39 cw(c399.61,2120.07) 379.93,2120.07 cw(c399.62,2120.07)
  region: 399.61,2039.36 cw(c399.61,2019.67) 419.3,2019.68 cw(c399.61,2019.68) 399.61,1999.99 cw(c399.61,2019.67) 379.93,2019.67 cw(c399.62,2019.67)
  region: 297.21,1980.26 cw(c297.21,1960.57) 316.9,1960.58 cw(c297.21,1960.58) 297.21,1940.89 cw(c297.21,1960.57) 277.53,1960.57 cw(c297.22,1960.57)
  region: 968.51,1649.56 cw(c968.51,1629.87) 988.2,1629.88 cw(c968.51,1629.88) 968.51,1610.19 cw(c968.51,1629.87) 948.83,1629.87 cw(c968.52,1629.87)
  region: 1427.11,1478.26 cw(c1427.11,1458.57) 1446.8,1458.58 cw(c1427.11,1458.58) 1427.11,1438.89 cw(c1427.11,1458.57) 1407.43,1458.57 cw(c1427.12,1458.57)
  region: 1535.41,1478.26 cw(c1535.41,1458.57) 1555.1,1458.58 cw(c1535.41,1458.58) 1535.41,1438.89 cw(c1535.41,1458.57) 1515.73,1458.57 cw(c1535.42,1458.57)
  region: 1637.81,1511.76 cw(c1637.81,1492.07) 1657.5,1492.08 cw(c1637.81,1492.08) 1637.81,1472.39 cw(c1637.81,1492.07) 1618.13,1492.07 cw(c1637.82,1492.07)
  region: 1734.21,1537.36 cw(c1734.21,1517.67) 1753.9,1517.68 cw(c1734.21,1517.68) 1734.21,1497.99 cw(c1734.21,1517.67) 1714.53,1517.67 cw(c1734.22,1517.67)
  region: 1679.11,1729.26 cw(c1679.11,1709.57) 1698.8,1709.58 cw(c1679.11,1709.58) 1679.11,1689.89 cw(c1679.11,1709.57) 1659.43,1709.57 cw(c1679.12,1709.57)
  region: 1730.31,1814.96 cw(c1730.31,1795.27) 1750,1795.28 cw(c1730.31,1795.28) 1730.31,1775.59 cw(c1730.31,1795.27) 1710.63,1795.27 cw(c1730.32,1795.27)
  region: 726.21,1830.86 cw(c726.21,1811.17) 745.9,1811.18 cw(c726.21,1811.18) 726.21,1791.49 cw(c726.21,1811.17) 706.53,1811.17 cw(c726.22,1811.17)

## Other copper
Top Layer:
  pour cut-out: 2926.18,106.3 2931.1,111.22 2999.02,111.22 2999.02,99.41 2925.2,99.41 2925.2,105.31 2926.18,106.3 2926.27,106.3 2927.44,107.47 2927.44,107.56 2928.15,108.27
  pour cut-out: 2696.85,1788.39 2670.28,1810.04 2691.93,1861.22 2703.74,1861.22 2703.74,1787.4 2697.83,1787.4 2696.85,1788.39 2696.85,1788.48 2695.68,1789.65 2695.59,1789.65 2694.88,1790.35
  pour cut-out: 2715.55,983.27 2720.47,988.19 2788.39,988.19 2788.39,976.38 2714.57,976.38 2714.57,982.28 2715.55,983.27 2715.64,983.27 2716.81,984.44 2716.81,984.53 2717.52,985.24
  pour cut-out: 2622.05,958.66 2626.97,953.74 2626.97,924.21 2615.16,924.21 2599.41,963.58 2621.06,959.65 2622.05,958.66 2622.05,958.57 2623.22,957.4 2623.31,957.4 2624.02,956.69
  pour cut-out: 628.94,2178.15 662.4,2178.15 662.4,2165.35 656.5,2159.45 629.92,2159.45 627.95,2161.42
  pour cut-out: 1209.65,935.04 1214.57,939.96 1244.09,939.96 1244.09,928.15 1208.66,928.15 1208.66,934.06 1209.65,935.04 1209.74,935.04 1210.91,936.21 1210.91,936.3 1211.61,937.01
  pour cut-out: 2639.76,906.5 2644.69,911.42 2712.6,911.42 2712.6,899.61 2638.78,899.61 2638.78,905.51 2639.76,906.5 2639.86,906.5 2641.03,907.67 2641.03,907.76 2641.73,908.46
  pour cut-out: 2539.37,1222.44 2544.29,1227.36 2573.82,1227.36 2573.82,1215.55 2538.39,1215.55 2538.39,1221.46 2539.37,1222.44 2539.46,1222.44 2540.63,1223.61 2540.63,1223.7 2541.34,1224.41
  pour cut-out: 2564.96,1245.08 2569.88,1250 2599.41,1250 2599.41,1238.19 2563.98,1238.19 2563.98,1244.09 2564.96,1245.08 2565.05,1245.08 2566.22,1246.25 2566.22,1246.34 2566.93,1247.05
  pour cut-out: 2494.09,1187.01 2499.02,1191.93 2528.54,1191.93 2528.54,1180.12 2493.11,1180.12 2493.11,1186.02 2494.09,1187.01 2494.19,1187.01 2495.36,1188.18 2495.36,1188.27 2496.06,1188.98
  pour cut-out: 2519.68,1068.9 2524.61,1073.82 2554.13,1073.82 2554.13,1062.01 2518.7,1062.01 2518.7,1067.91 2519.68,1068.9 2519.78,1068.9 2520.95,1070.07 2520.95,1070.16 2521.65,1070.87
  pour cut-out: 2577.76,1378.94 2582.68,1383.86 2612.2,1383.86 2612.2,1351.38 2589.57,1342.52 2569.88,1383.86 2577.76,1378.94 2577.85,1378.94 2579.02,1380.11 2579.02,1380.2 2579.72,1380.91
  pour cut-out: 3289.37,1382.87 3294.29,1377.95 3294.29,1348.43 3282.48,1348.43 3282.48,1383.86 3288.39,1383.86 3289.37,1382.87 3289.37,1382.78 3290.54,1381.61 3290.63,1381.61 3291.34,1380.91
  pour cut-out: 3173.23,1341.54 3178.15,1336.61 3178.15,1307.09 3166.34,1307.09 3166.34,1342.52 3172.24,1342.52 3173.23,1341.54 3173.23,1341.44 3174.4,1340.27 3174.49,1340.27 3175.2,1339.57
  pour cut-out: 1224.41,1284.45 1224.41,1300.2 1236.22,1300.2 1242.13,1294.29 1242.13,1289.37 1230.32,1289.37 1227.36,1286.42
  pour cut-out: 1260.83,1323.82 1257.87,1320.87 1257.87,1317.91 1263.78,1312.01 1266.73,1312.01 1266.73,1323.82
  pour cut-out: 1015.75,1337.6 1021.65,1337.6 1021.65,1334.65 1020.67,1333.66 1013.78,1333.66 1013.78,1335.63
  pour cut-out: 1085.63,1343.5 1094.49,1343.5 1094.49,1333.66 1093.5,1332.68 1092.52,1333.66 1086.61,1333.66 1086.61,1342.52
  pour cut-out: 1040.35,1324.8 1043.31,1324.8 1043.31,1320.87 1040.35,1320.87
  pour cut-out: 1037.4,1337.6 1044.29,1337.6 1044.29,1334.65 1042.32,1332.68 1038.39,1332.68 1038.39,1336.61
  region net BC_I2C_EXP_SDA: 4216.92,1701.18 4207.08,1691.34 4207.08,1624.41 4225.78,1605.71 4359.64,1605.71 4376.37,1622.44 4376.37,1696.26 4371.45,1701.18
  region net 3V3: 4022.04,1701.18 3998.03,1677.17 3998.03,1632.87 4025.2,1605.71 4172.64,1605.71 4180.12,1613.19 4180.12,1683.07 4162.01,1701.18
  region net GND: 4219.49,767.72 4208.66,756.89 4208.66,686.8 4234.64,660.83 4368.5,660.83 4385.23,677.56 4385.23,751.38 4368.89,767.72
  region net VMCU: 4022.64,755.91 4012.8,746.06 4012.8,679.13 4031.5,660.43 4165.35,660.43 4182.09,677.17 4182.09,750.98 4177.17,755.91
  pour cut-out: 2427.17,1418.31 2418.31,1418.31 2398.62,1398.62 2395.67,1401.57 2395.67,1405.51 2401.57,1405.51 2420.28,1424.21
  pour cut-out: 1617.13,1848.43 1619.09,1846.46 1619.09,1830.71 1635.83,1830.71 1637.8,1832.68 1630.91,1839.57 1630.91,1854.33
  pour cut-out: 1624.02,1893.7 1623.03,1892.72 1623.03,1874.02 1634.84,1874.02 1632.87,1875.98 1632.87,1895.67 1627.95,1895.67 1626.97,1894.69
  pour cut-out: 1576.77,1577.76 1576.77,1581.69 1596.46,1601.38 1594.49,1603.35 1583.66,1603.35 1583.66,1597.44 1568.9,1582.68
  pour cut-out: 1186.02,1895.67 1225.39,1895.67 1225.39,1894.69 1224.41,1893.7 1187.01,1893.7 1187.01,1895.67 1186.02,1896.65
  pour cut-out: 1030.51,1839.57 1026.57,1835.63 1026.57,1805.12 1019.69,1805.12 1018.7,1806.1 1022.64,1810.04 1022.64,1839.57 1025.59,1839.57 1026.57,1840.55
  pour cut-out: 378.94,2186.02 428.15,2186.02 427.17,2185.04 427.17,2183.07 378.94,2183.07 377.95,2184.06
  pour cut-out: 942.91,1275.59 942.91,1261.81 948.82,1261.81 948.82,1275.59
  pour cut-out: 854.33,1073.48 874.02,1073.48 874.02,1027.56 854.33,1027.56
  region net N17481376: 415.05,1034.44 415.05,1161.41 136.31,1161.41 136.31,1034.44
  region net N17481376: 136.13,304.15 136.13,218.2 177.15,177.18 414.87,177.18 414.87,304.15
Signal Layer 3:
  pour cut-out: 3655.51,1195.99 3655.51,1129.92 3655.51,1127.95 3606.3,1127.95 3606.3,1189.84
  pour cut-out: 2646.65,346.46 2646.65,262.8 2641.73,257.87 2638.78,260.83 2638.78,345.47
  pour cut-out: 2573.82,375 2573.82,291.34 2568.9,286.42 2565.94,289.37 2565.94,374.02
  pour cut-out: 2142.72,2024.61 2142.72,1974.41 2141.73,1973.43 2132.87,1982.28 2132.87,2025.59 2140.75,2033.46
  pour cut-out: 1700.3,2018.21 1698.82,2019.69 1698.82,2147.64 1705.71,2143.7 1705.71,2012.8
  pour cut-out: 1979.33,1897.64 1983.27,1901.57 1983.27,2050.2 1990.16,2050.2 1990.16,1902.56
  pour cut-out: 3097.44,1086.86 3097.44,978.35 3092.52,973.43 3089.57,976.38 3089.57,1085.88
  pour cut-out: 1930.12,1688.98 1930.12,1605.32 1925.2,1600.39 1887.8,1637.8 1922.24,1687.99
  pour cut-out: 2588.58,1750 2588.58,1666.34 2583.66,1661.42 2580.71,1664.37 2580.71,1749.02
  pour cut-out: 2455.71,1816.93 2455.71,1652.56 2419.29,1688.98 2419.29,1773.62
  pour cut-out: 3539.37,1211.74 3539.37,1145.67 3539.37,1143.7 3490.16,1143.7 3490.16,1205.59
  pour cut-out: 3493.11,874.75 3493.11,704.72 3488.19,699.8 3485.24,702.76 3485.24,873.77
  pour cut-out: 2225.87,401.57 2195.11,317.8 1941.72,339.55 1995.33,401.57
  pour cut-out: 2469.49,662.4 2469.49,578.74 2464.57,573.82 2461.61,576.77 2461.61,661.42
  pour cut-out: 2570.87,656.5 2570.87,572.83 2562.99,530.51 2562.99,570.87 2562.99,655.51
  pour cut-out: 2125.98,1022.64 2129.92,1018.7 2132.87,1021.65 2132.87,1124.02 2124.02,1124.02 2125.98,1122.05 2125.98,1120.08
  pour cut-out: 1562.99,1297.24 1562.99,1260.83 1561.02,1258.86 1561.02,1297.24
  pour cut-out: 1826.77,1549.21 1952.76,1549.21 1952.76,1552.17 1826.77,1552.17 1824.8,1554.13
  pour cut-out: 1724.41,1483.27 1774.61,1483.27 1774.61,1487.2 1773.62,1488.19 1724.41,1488.19
  pour cut-out: 1993.11,1271.65 2059.06,1271.65 2060.04,1272.64 2060.04,1276.57 1993.11,1276.57 1991.14,1274.61
  pour cut-out: 2382.87,1295.28 2382.87,1247.05 2379.92,1250 2379.92,1295.28
  pour cut-out: 2445.87,1362.2 2445.87,1323.82 2444.88,1322.83 2443.9,1323.82 2443.9,1363.19
  pour cut-out: 2407.48,1583.66 2407.48,1515.75 2405.51,1513.78 2401.57,1517.72 2401.57,1587.6
  pour cut-out: 2736.22,942.91 2736.22,909.45 2729.33,916.34 2730.32,917.32 2730.32,944.88
  pour cut-out: 1989.17,1717.52 1989.17,1667.32 1988.19,1666.34 1979.33,1675.2 1979.33,1718.5 1987.2,1726.38
  pour cut-out: 1758.86,2140.75 1762.8,2136.81 1911.42,2136.81 1911.42,2129.92 1763.78,2129.92
  pour cut-out: 2705.71,1800.2 2704.72,1799.21 2704.72,1727.36 2700.79,1727.36 2696.85,1731.3 2699.8,1734.25 2699.8,1800.2
  pour cut-out: 4008.86,959.65 4026.57,959.65 4026.57,967.52 4025.59,966.54 4010.83,966.54 4010.83,963.58 4009.84,962.6
  pour cut-out: 2859.25,1572.83 2886.81,1572.83 2886.81,1574.8 2883.86,1577.76 2862.2,1577.76
  pour cut-out: 2579.72,1180.12 2579.72,1183.07 2607.28,1210.63 2604.33,1213.58 2600.39,1213.58 2600.39,1212.6 2574.8,1187.01
  pour cut-out: 2830.71,1346.46 2832.68,1358.27 2834.65,1219.49 2834.65,1220.47 2832.68,1222.44 2832.68,1326.77
  pour cut-out: 2005.91,622.05 2005.91,609.25 2013.78,601.38 2015.75,603.35 2015.75,618.11
  pour cut-out: 1686.02,846.46 1686.02,809.06 1679.13,802.17 1679.13,850.39
  pour cut-out: 1152.56,994.09 1153.54,993.11 1153.54,949.8 1163.39,949.8 1165.35,951.77 1159.45,957.68 1159.45,999.02
  pour cut-out: 2048.23,1175.2 2048.23,1136.81 2049.21,1137.8 2051.18,1137.8 2051.18,1172.24
  pour cut-out: 1533.46,1297.24 1533.46,1298.23 1532.48,1297.24 1531.5,1297.24
  pour cut-out: 1330.71,1424.21 1330.71,1379.92 1331.69,1378.94 1332.68,1379.92 1335.63,1379.92 1335.63,1422.24 1333.66,1424.21
  pour cut-out: 1291.34,1873.03 1290.35,1874.02 1290.35,1902.56 1301.18,1902.56 1297.24,1898.62 1297.24,1873.03
Signal Layer 4:
  pour cut-out: 2599.27,1335.7 2518.56,1335.7 2525.45,1342.59 2602.22,1342.59
  pour cut-out: 3584.51,1447.9 3503.8,1447.9 3510.69,1454.79 3587.46,1454.79
  pour cut-out: 3353.21,1049.28 3272.5,1049.28 3279.39,1056.17 3356.16,1056.17
  pour cut-out: 3417.18,1130.97 3336.47,1130.97 3343.36,1137.86 3420.14,1137.86
  pour cut-out: 3687.85,1267.78 3607.14,1267.78 3614.03,1274.67 3690.8,1274.67
  pour cut-out: 3628.8,1075.85 3548.09,1075.85 3554.98,1082.74 3631.75,1082.74
  pour cut-out: 3533.46,953.74 3452.76,953.74 3459.65,960.63 3536.42,960.63
  pour cut-out: 1919.43,1964.57 1864.17,1964.57 1862.2,1966.54 1867.13,1971.46 1922.38,1971.46
  pour cut-out: 1937.01,1757.87 1910.43,1757.87 1908.46,1759.84 1913.39,1764.76 1939.96,1764.76
  pour cut-out: 2643.42,795.28 2608.27,795.28 2604.82,798.72 2608.27,802.17 2646.37,802.17
  pour cut-out: 3180.54,925.69 3056.1,918.31 3166.3,911.45
  pour cut-out: 2399.61,1318.9 2204.72,1318.9 2201.77,1321.85 2202.76,1322.83 2202.76,1331.69 2388.78,1331.69 2391.73,1328.74
  pour cut-out: 2158.46,2027.56 2158.46,1974.41 2151.57,1974.41 2149.61,1976.38 2155.51,1982.28 2155.51,2027.56
  pour cut-out: 2441.93,1815.94 2428.15,1802.17 2367.13,1863.19 2367.13,1890.75
  pour cut-out: 2828.46,984.25 2780.51,984.25 2778.54,986.22 2783.46,991.14 2831.41,991.14
  pour cut-out: 3958.66,2028.54 3958.66,1993.11 3956.69,1991.14 3953.74,1994.09 3953.74,2023.62 3957.68,2027.56
  pour cut-out: 3355.31,1966.54 3298.23,1966.54 3298.23,2011.81 3355.31,2011.81
  pour cut-out: 3291.34,1516.73 3338.58,1516.73 3339.57,1517.72 3341.54,1515.75 3341.54,1507.87 3297.24,1507.87 3292.32,1512.8
  pour cut-out: 2764.76,1908.46 2765.75,1909.45 2796.26,1909.45 2796.26,1899.61 2794.29,1897.64 2788.39,1903.54 2760.83,1903.54 2760.83,1909.45 2763.78,1912.4
  pour cut-out: 2442.91,1413.39 2438.98,1409.45 2438.98,1324.8 2436.02,1324.8 2429.13,1331.69 2432.09,1334.65 2432.09,1415.35
  pour cut-out: 1635.83,1869.09 1689.96,1869.09 1692.91,1866.14 1691.93,1865.16 1639.76,1865.16
  pour cut-out: 1662.4,1311.02 1731.3,1311.02 1700.79,1320.87 1700.79,1321.85 1660.43,1321.85 1656.5,1317.91
  pour cut-out: 1831.69,1064.96 1878.94,1064.96 1883.86,1069.88 1880.91,1072.83 1829.72,1072.83
VCC Layer 5:
  pour cut-out: 31.67,1417.5 18.7,1404.53 18.7,1418.31
  pour cut-out: 31.5,1422.24 17.72,1436.02 17.72,1422.24 26.57,1422.24
  pour cut-out: 277.56,2343.5 294.29,2326.77 298.23,2326.77 298.23,2344.49 297.24,2345.47 296.26,2344.49 278.54,2344.49
Bottom Layer:
  pour cut-out: 2733.66,1730.96 2785.43,1754.92 2756.42,1683.59 2738.58,1701.43 2731.7,1708.32 2711.03,1708.32
  pour cut-out: 2765.16,1598.08 2774.02,1589.23 2805.75,1501.34 2738.19,1518.7 2763.19,1595.13
  pour cut-out: 2671.66,1776.23 2680.51,1767.38 2694.42,1728.87 2676.58,1746.71 2669.69,1753.6 2669.69,1773.28
  pour cut-out: 2654.92,1509.5 2663.78,1500.64 2663.78,1479.97 2659.84,1479.97 2652.95,1486.86 2652.95,1506.55
  pour cut-out: 1919.29,1163.39 1924.21,1158.46 1942.91,1158.46
  pour cut-out: 1899.61,1723.43 1904.53,1728.35 1904.53,1747.05
  pour cut-out: 1810.04,1712.6 1814.96,1707.68 1841.54,1707.68
  pour cut-out: 1764.76,1674.21 1759.84,1669.29 1759.84,1650.59
  pour cut-out: 2183.07,1455.71 2177.17,1455.71 2165.35,1443.9 2165.35,1451.77 2171.26,1451.77 2178.15,1458.66
  pour cut-out: 2171.26,1837.6 2174.21,1834.65 2174.21,1768.7 2171.26,1768.7 2170.28,1769.69 2171.26,1770.67
  pour cut-out: 1691.93,1060.04 1691.93,999.02 1690.94,998.03 1693.9,998.03 1693.9,1058.07 1695.87,1060.04
  pour cut-out: 1728.35,1385.83 1732.28,1381.89 1792.32,1381.89 1792.32,1386.81 1790.35,1388.78 1732.28,1388.78
  pour cut-out: 1906.5,1322.83 1905.51,1321.85 1905.51,1319.88 1881.89,1319.88 1878.94,1322.83
  pour cut-out: 2069.88,1578.74 2041.34,1578.74 2041.34,1580.71 2043.31,1582.68 2066.93,1582.68
  pour cut-out: 1953.74,1673.23 1953.74,1611.22 1954.72,1610.24 1956.69,1612.2 1960.63,1612.2 1960.63,1665.35 1959.65,1666.34
  pour cut-out: 1644.68,1731.3 1639.76,1736.22 1621.06,1736.22
  pour cut-out: 492.13,2094.49 482.28,2084.65 482.28,2082.68 474.41,2090.55 484.25,2100.39 489.17,2100.39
